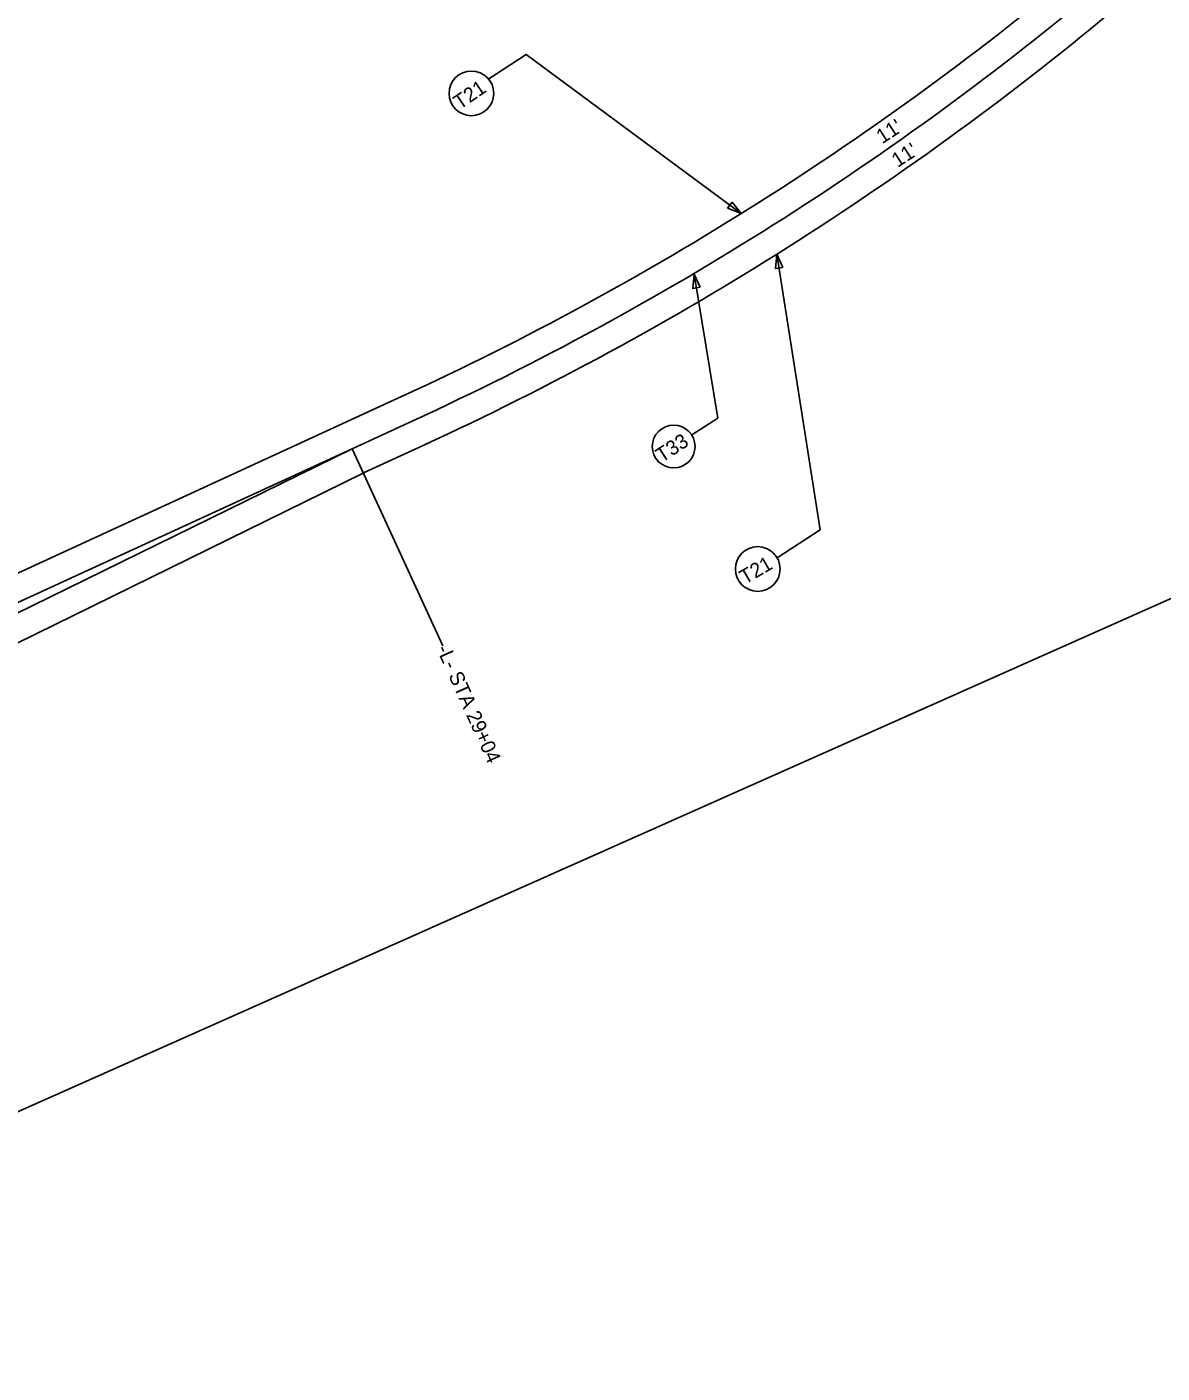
# Model space of a CAD drawing. Extents: x 553958 to 562499, y 493978 to 516388.
# Drawn here: x 555983 to 556451, y 503591 to 504146 of the extents above; entities that cross this region are included whole.
import ezdxf

# ---------------------------------------------------------------- set-up
doc = ezdxf.new("R2010")
doc.units = 0
for name, color, linetype in [('Prop Approach Slab', 7, 'Continuous'), ('Prop EOT', 7, 'Continuous'), ('Prop Erosion Rip Rap Class II Label', 7, 'Continuous'), ('Raster_Level_0', 7, 'Continuous'), ('Sheet Plan CELL', 7, 'Continuous'), ('Sheet Plot Border Inside CELL', 7, 'Continuous')]:
    doc.layers.add(name, color=color, linetype=linetype)

msp = doc.modelspace()

# ---------------------------------------------------------------- linework, layer by layer
at = {"layer": 'Prop Approach Slab'}
msp.add_line((556154.14, 503890.56), (556116.75, 503971.82), dxfattribs=at)
at = {"layer": 'Prop Erosion Rip Rap Class II Label'}
msp.add_lwpolyline([(555736.45, 503590.64), (555435.27, 504245.31), (556565.58, 504822.05), (556936.88, 504379.27), (556608.88, 503978.75)], close=True, dxfattribs=at)
at = {"layer": 'Raster_Level_0'}
for p, q in [((556116.75, 503971.82), (556141.73, 503983.31)), ((555635.07, 503750.23), (556116.75, 503971.82)), ((555725.52, 503779.73), (556116.75, 503971.82))]:
    msp.add_line(p, q, dxfattribs=at)
msp.add_arc((555610.95, 505137.08), 1270, 294.70456, 309.98225, dxfattribs=at)
at = {"layer": 'Sheet Plan CELL'}
for points in [[(556173.06, 504124.34), (556188.5, 504134.37), (556277.16, 504068.79)], [(556291.97, 503926.86), (556309.76, 503938.42), (556291.9, 504052.06)], [(556256.75, 503977.5), (556267.48, 503984.47), (556257.8, 504043.86)]]:
    msp.add_lwpolyline(points, dxfattribs=at)
for points in [[(556271.57, 504070.98), (556277.16, 504068.79), (556273.42, 504073.48)], [(556294.33, 504046.57), (556291.9, 504052.06), (556291.26, 504046.09)], [(556260.26, 504038.39), (556257.8, 504043.86), (556257.2, 504037.89)]]:
    msp.add_lwpolyline(points, close=True, dxfattribs=at)
for centre, radius in [((556165.91, 504118.36), 9.22), ((556249.34, 503972.7), 8.82), ((556284, 503922.23), 9.22)]:
    msp.add_circle(centre, radius, dxfattribs=at)
at = {"layer": 'Sheet Plot Border Inside CELL'}
for p, q in [((555898.02, 503883.31), (556137.13, 503993.31)), ((556121.35, 503961.83), (556146.33, 503973.32)), ((556121.24, 503961.78), (555730.17, 503769.76))]:
    msp.add_line(p, q, dxfattribs=at)
for radius in [1259, 1281]:
    msp.add_arc((555610.95, 505137.08), radius, 294.70456, 309.98225, dxfattribs=at)

# ---------------------------------------------------------------- texts
at = {"layer": 'Prop EOT'}
for p in [(556335.37, 504097.38), (556341.71, 504087.61)]:
    msp.add_text("11'", height=6, rotation=33.0007, dxfattribs=at).set_placement(p)
at = {"layer": 'Sheet Plan CELL'}
for s, rotation, p in [('T21', 34.2487, (556161.13, 504111.47)), ('T33', 33.0007, (556244.44, 503965.93)), ('T21', 30.1931, (556278.75, 503915.7)), ('-L- STA 29+04', 294.1816, (556151.4, 503889.33))]:
    msp.add_text(s, height=6, rotation=rotation, dxfattribs=at).set_placement(p)

doc.saveas('drawing.dxf')
